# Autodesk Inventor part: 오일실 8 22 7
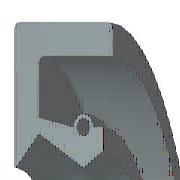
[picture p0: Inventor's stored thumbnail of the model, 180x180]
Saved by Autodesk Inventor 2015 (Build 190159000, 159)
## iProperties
IsCustomPart: 1
Created: 2012-02
Part Number: 오일실 8 22 7
Material: 고무
Description: 오일-실
Document SubType Name: Modeling
Standard: KS B 2804
Designer: mduedu
Standards Organization: KS
Language: ko-KR
Size Designation: D - 8 22 7
Categories: <MemberInstance><Categories><Category DisplayName="샤프트 부품" InternalName="7f7aeb1f-a693-4053-b835-cee3144e0d98" Mnemonic="SHFT"><Category DisplayName="실링" Intern
Density: 0.93 g/cm^3
Mass: 1.28441 g
Surface Area: 18.2787 cm^2
Volume: 1.38108 cm^3
Appearance: 고무 - 검은색 - 버전 1.1
Author: mduedu
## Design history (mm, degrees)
revolve "본체" stored, may be unused: angle "d17" = 90 deg
revolve "스프링1" stored, may be unused: angle "d18" = 90 deg
body "Solid1"
sketch "스케치1"
  geometry: L1 (0, 11)-(7, 11); L2 (7, 9.25)-(1.75, 9.25); L3 (1.75, 5.75)-(4.9, 4); L4 (4.9, 4)-(0, 4); L5 (0, 0)-(9.586, 0) reference; L6 (4.9, 4)-(6.3, 4.875); L7 (0, 18)-(0, -3) reference; L8 (-1.941, 0)-(11.507, 0) reference; L9 (4.2, 6.1)-(1.75, 6.59); L10 (1.75, 6.59)-(1.75, 9.25); L11 (0, 11)-(0, 4.088); L12 (4.9, 4)-(0, 4); L13 (1.75, 5.75)-(0.152, 4.028); L14 (7, 11)-(7, 9.25); L15 (5.6, 6.1)-(6.3, 6.1); L16 (6.3, 6.1)-(6.3, 4.875); C1 r 0.455 at (4.9, 6.1); A1 r 0.7 centre (4.9, 6.1) between (5.6, 6.1) and (4.2, 6.1); A2 r 0.088 centre (0.088, 4.088) between (0, 4.088) and (0.152, 4.028); 1 further point
  constraints: 28 end point, 5 horizontal alignment, 5 point on line, 4 point on circle, 4 vertical alignment, 3 centre point, 3 tangent, 2 collinear, 2 horizontal, 2 perpendicular, 1 coincident, 1 parallel
  dimensions: "d0" = 22 diameter of L1 L5 (= SD2); "d1" = 1.75 distance of L1.end L2.start (= SD); "d2" = 0.91 diameter of C1 (= SPDI); "d3" = 1.4 diameter of A1 (= SPDA); "d4" = 8 diameter of L3.end L5 (= NND); "d5" = 11.5 diameter of L3.start L5 (= TKDM); "d7" = 13.18 diameter of L9.end L5 (= TKDM + 0.24 x SWDT); "d8" = 1.75 distance between parallel lines of L11 L10 (= SD); "d9" = 4.9 distance from line of L11 C1.centre (= SPDST); "d10" = 12.2 diameter of C1.centre L5 (= HLDM); "d11" = 0.0875 radius of A2 (= 0.25 x LAB); "d12" = 6.3 distance between parallel lines of L11 L16 (= SDI); "d13" = 9.75 diameter of L6.end L5 (= ABDM); "d14" = 7 distance from line of L11 L1.end (= SWDT)
fillet "모깎기1" dims "d6" = 0.3 (= RR)
other parameters: "SD2" = 22 [user parameter; used in 1 equation term], "SWDT" = 7 [user parameter; used in 2 equation terms], "RR" = 0.3 [user parameter; used in 1 equation term], "SD" = 1.75 [user parameter; used in 2 equation terms], "NND" = 8 [user parameter; used in 1 equation term], "SPDA" = 1.4 [user parameter; used in 1 equation term], "SPDI" = 0.91 [user parameter; used in 1 equation term], "TKDM" = 11.5 [user parameter; used in 2 equation terms], "HLDM" = 12.2 [user parameter; used in 1 equation term], "ABDM" = 9.75 [user parameter; used in 1 equation term], "SDI" = 6.3 [user parameter; used in 1 equation term], "SPDST" = 4.9 [user parameter; used in 1 equation term], "LAB" = 0.35 [user parameter; used in 1 equation term], "d15" = 0, "d16" = 0, "d19" = 0
